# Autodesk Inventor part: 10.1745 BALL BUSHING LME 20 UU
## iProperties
Created: 2007-06
Part Number: 10.1745 BALL BUSHING LME 20 UU
Material: Steel
Document SubType Name: Modeling
Designer: Andy Moles
Density: 7.85 g/cm^3
Author: Andy Moles
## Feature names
1. Extrusion1
2. Revolution1
3. Extrusion2
4. Mirror1
5. Chamfer1
